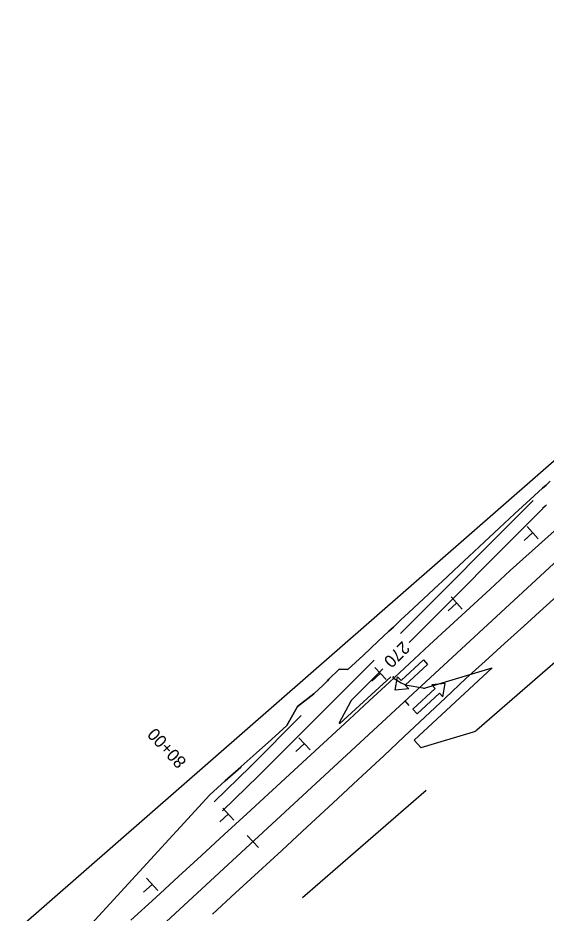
# Model space of a CAD drawing. Extents: x 1710723 to 1713003, y 548603 to 551142.
# Drawn here: x 1710723.1 to 1710978, y 548872.8 to 549304.6 of the extents above; entities that cross this region are included whole.
import ezdxf

# ---------------------------------------------------------------- set-up
doc = ezdxf.new("R2010")
doc.units = 0
for name, color, linetype in [('R_Contour Annot', 7, 'Continuous'), ('R_Contours', 7, 'Continuous'), ('R_Horz Alg', 7, 'Continuous'), ('R_Horz Alg Annot', 7, 'Continuous'), ('R_MOT', 7, 'Continuous'), ('R_No Plot', 7, 'Continuous')]:
    doc.layers.add(name, color=color, linetype=linetype)

msp = doc.modelspace()

# ---------------------------------------------------------------- linework, layer by layer
at = {"layer": 'R_Contours'}
for points in [[(1710907.67, 549007.57), (1710971.81, 549071.85)], [(1710978.2, 549069.74), (1710977.98, 549069.52), (1710977.75, 549069.29), (1710977.52, 549069.06), (1710976.33, 549067.89), (1710976.24, 549067.8), (1710976.15, 549067.71), (1710976.06, 549067.62), (1710975.97, 549067.53), (1710911.92, 549003.33)], [(1710904.2, 548987.11), (1710904.07, 548986.48), (1710904.06, 548986.39), (1710904.08, 548986.31), (1710904.13, 548986.24), (1710904.2, 548986.19), (1710908.06, 548983.85), (1710908.75, 548983.47), (1710909.46, 548983.16), (1710910.19, 548982.92), (1710910.95, 548982.75), (1710918.52, 548981.36), (1710918.86, 548981.31), (1710919.2, 548981.31), (1710919.54, 548981.35), (1710919.87, 548981.43), (1710951.95, 548991.06), (1710952, 548991.07), (1710952.02, 548991.06), (1710952.01, 548991.04), (1710951.98, 548991.01), (1710914.35, 548956.26), (1710914.32, 548956.23), (1710914.31, 548956.2), (1710914.32, 548956.16), (1710914.34, 548956.13), (1710917.53, 548952.67), (1710917.57, 548952.63), (1710917.62, 548952.61), (1710917.67, 548952.61), (1710917.73, 548952.62), (1710942.98, 548960.19), (1710943.43, 548960.36), (1710943.85, 548960.56), (1710944.25, 548960.81), (1710944.63, 548961.1), (1711016.51, 549023.49)], [(1710821.89, 548922.06), (1710839.22, 548938.97), (1710839.38, 548939.12), (1710839.53, 548939.28), (1710839.68, 548939.43), (1710839.84, 548939.58), (1710894.96, 548994.83)], [(1710899.2, 548990.59), (1710883.99, 548975.34), (1710883.86, 548975.2), (1710883.75, 548975.06), (1710883.64, 548974.91), (1710883.55, 548974.75), (1710878.19, 548964.59), (1710878.17, 548964.55), (1710878.17, 548964.51), (1710878.18, 548964.47), (1710878.21, 548964.43), (1710878.42, 548964.2), (1710878.42, 548964.2), (1710903.05, 548986.75)], [(1710817.82, 548926.48), (1710835.33, 548943.56), (1710835.4, 548943.62), (1710835.47, 548943.69), (1710835.53, 548943.76), (1710835.6, 548943.82), (1710859.86, 548968.14)], [(1710920.17, 548931.93), (1710860.48, 548880.13)]]:
    msp.add_lwpolyline(points, dxfattribs=at)
at = {"layer": 'R_Horz Alg'}
msp.add_line((1710761.95, 548838.38), (1710989.21, 549048.39), dxfattribs=at)
at = {"layer": 'R_Horz Alg Annot'}
for points in [[(1710912, 548972.96), (1710909.97, 548975.16)], [(1710833.81, 548910.23), (1710839.24, 548904.35)]]:
    msp.add_lwpolyline(points, dxfattribs=at)
at = {"layer": 'R_MOT'}
for p, q in [((1710968.84, 549059.19), (1710974.25, 549053.29)), ((1710971.44, 549056.18), (1710967.42, 549052.49)), ((1710934.72, 549022.24), (1710930.7, 549018.55)), ((1710932.12, 549025.26), (1710937.53, 549019.36)), ((1710898, 548988.31), (1710893.98, 548984.62)), ((1710895.4, 548991.32), (1710900.8, 548985.42)), ((1710858.68, 548957.39), (1710864.08, 548951.49)), ((1710861.28, 548954.37), (1710857.26, 548950.69)), ((1710821.96, 548923.45), (1710827.36, 548917.55)), ((1710824.56, 548920.44), (1710820.53, 548916.75)), ((1710785.19, 548889.57), (1710790.6, 548883.67)), ((1710787.8, 548886.56), (1710783.77, 548882.87))]:
    msp.add_line(p, q, dxfattribs=at)
for points in [[(1710777.62, 548869.39), (1710789.67, 548880.34), (1710800.65, 548890.43), (1710811.64, 548900.53), (1710822.62, 548910.62), (1710833.61, 548920.71), (1710845.94, 548932.07), (1710858.28, 548943.43), (1710870.62, 548954.79), (1710882.95, 548966.15), (1710892.67, 548975.17), (1710902.38, 548984.19), (1710912.1, 548993.2), (1710921.81, 549002.22), (1710931.54, 549011.16), (1710941.27, 549020.11), (1710951, 549029.06), (1710960.74, 549038), (1710977.43, 549053), (1710994.12, 549067.99), (1711010.82, 549082.98), (1711027.51, 549097.98), (1711032.63, 549102.38)], [(1710980.05, 549081.16), (1710977.97, 549079.29), (1710976.21, 549077.7), (1710972.4, 549074.21), (1710970.21, 549072.2), (1710968.59, 549070.7), (1710962.8, 549065.34), (1710955.45, 549058.55), (1710948.12, 549051.75), (1710940.82, 549044.92), (1710933.51, 549038.09), (1710927.67, 549032.6), (1710926.21, 549031.25), (1710918.91, 549024.42), (1710911.79, 549017.8), (1710911.59, 549017.61), (1710907.95, 549014.19), (1710904.29, 549010.77), (1710902.1, 549008.73), (1710896.99, 549003.94), (1710889.69, 548997.11), (1710882.38, 548990.28)], [(1710882.38, 548990.28), (1710878.09, 548990.5), (1710873.14, 548985.54), (1710872.44, 548984.83), (1710870.35, 548982.74), (1710865.95, 548978.59), (1710858.03, 548972.43), (1710852.9, 548963.24)], [(1710852.9, 548963.24), (1710845.47, 548956.55), (1710838.05, 548949.85), (1710830.91, 548943.43), (1710830.61, 548943.16), (1710823.15, 548936.5), (1710815.76, 548929.77), (1710815.76, 548929.77)], [(1710815.76, 548929.77), (1710747.87, 548855.88), (1710754.66, 548848.54)]]:
    msp.add_lwpolyline(points, dxfattribs=at)
for points in [[(1710911.74, 548980.89), (1710905.22, 548980.3), (1710906.32, 548986.76), (1710908.01, 548984.93), (1710918.82, 548994.91), (1710920.85, 548992.71), (1710910.05, 548982.72)], [(1710928.24, 548977.07), (1710929.34, 548983.53), (1710922.81, 548982.94), (1710924.51, 548981.11), (1710913.7, 548971.12), (1710915.74, 548968.92), (1710926.54, 548978.9)]]:
    msp.add_lwpolyline(points, close=True, dxfattribs=at)
at = {"layer": 'R_No Plot'}
msp.add_line((1710723.07, 548865.06), (1711226.5, 549304.64), dxfattribs=at)
for points in [[(1710882.38, 548990.28), (1710889.69, 548997.11), (1710896.99, 549003.94), (1710902.1, 549008.73), (1710904.29, 549010.77), (1710907.95, 549014.19), (1710911.59, 549017.61), (1710911.79, 549017.8), (1710918.91, 549024.42), (1710926.21, 549031.25), (1710927.67, 549032.6), (1710933.51, 549038.09), (1710940.82, 549044.92), (1710948.12, 549051.75), (1710955.45, 549058.55), (1710962.8, 549065.34), (1710968.59, 549070.7), (1710970.21, 549072.2), (1710972.4, 549074.21), (1710976.21, 549077.7), (1710977.97, 549079.29), (1710980.05, 549081.16)], [(1710993.23, 549034.63), (1710976.56, 549019.63), (1710967.24, 549011.2), (1710957.92, 549002.77), (1710948.6, 548994.34), (1710939.28, 548985.91), (1710929.38, 548976.59), (1710919.47, 548967.26), (1710909.57, 548957.93), (1710899.67, 548948.6), (1710887.35, 548937.19), (1710875.03, 548925.79), (1710862.71, 548914.38), (1710850.39, 548902.97), (1710839.28, 548892.73), (1710828.17, 548882.48), (1710817.05, 548872.24)], [(1710993.23, 549034.63), (1710976.56, 549019.63), (1710967.24, 549011.2), (1710957.92, 549002.77), (1710948.6, 548994.34), (1710939.28, 548985.91), (1710929.38, 548976.59), (1710919.47, 548967.26), (1710909.57, 548957.93), (1710899.67, 548948.6), (1710887.35, 548937.19), (1710875.03, 548925.79), (1710862.71, 548914.38), (1710850.39, 548902.97), (1710839.28, 548892.73), (1710828.17, 548882.48), (1710817.05, 548872.24)], [(1710852.9, 548963.24), (1710858.03, 548972.43), (1710865.95, 548978.59), (1710870.35, 548982.74), (1710872.44, 548984.83), (1710873.14, 548985.54), (1710878.09, 548990.5), (1710882.38, 548990.28)], [(1710815.76, 548929.77), (1710815.76, 548929.77), (1710823.15, 548936.5), (1710830.61, 548943.16), (1710830.91, 548943.43), (1710838.05, 548949.85), (1710845.47, 548956.55), (1710852.9, 548963.24)], [(1710771.53, 548830.29), (1710747.87, 548855.88), (1710815.76, 548929.77)]]:
    msp.add_lwpolyline(points, dxfattribs=at)

# ---------------------------------------------------------------- texts
at = {"layer": 'R_Contour Annot'}
msp.add_text('270', height=6, rotation=225.0635, dxfattribs=at).set_placement((1710908.63, 549004.28))
at = {"layer": 'R_Horz Alg Annot'}
msp.add_text('80+00', height=6, rotation=132.7413, dxfattribs=at).set_placement((1710804.79, 548946.05))

doc.saveas('drawing.dxf')
